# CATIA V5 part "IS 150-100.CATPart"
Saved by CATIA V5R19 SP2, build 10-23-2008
Part number: IS 150-100
Bounding box of the stored display mesh (mm): x -15.868 to 15.868, y -15.868 to 15.868, z 0 to 250
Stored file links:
  C:\Users\Bora\Desktop\3D Katı model\IS serisi\IS 150\IS 150-100.CATPart
  C:\Program Files\Dassault Systemes\B19\intel_a\reffiles\standard\MetricThickPitch.txt
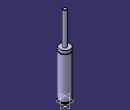
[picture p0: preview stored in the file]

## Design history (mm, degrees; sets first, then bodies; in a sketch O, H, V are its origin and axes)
Body1 (main body)
  Sketch1 on yz-plane, origin (0, 0, 0), H (0, 1, 0), V (0, 0, 1)
    point P3 (6, 249)
    point P5 (6, 249)
    point P7 (16, 138.5)
    point P8 (16, 136.5)
    point P12 (16, 136.5)
    point P13 (16, 138.5)
    line L1 (16, 0) -> (16, 4)
    line L2 (6, 249) -> (6, 148)
    arc A1 centre (5, 249) radius 1 from (6, 249) to (5, 250) ccw
    arc A2 centre (16, 137.5) radius 1 from (16, 138.5) to (16, 136.5) ccw
    line L3 (13.5, 7.5) -> (13.5, 4)
    line L4 (16, 7.5) -> (16, 136.5)
    line L5 (16, 138.5) -> (16, 148)
    line L6 (0, 0) -> (16, 0)
    line L7 (13.5, 4) -> (16, 4)
    line L8 (13.5, 7.5) -> (16, 7.5)
    line L9 (6, 148) -> (16, 148)
    line L10 (5, 250) -> (0, 250)
    point P15 (0, 250)
    horizontal: L6 H, L7 H, L8 H, L9 H
    tangency: L10 A1
    coincidence: P15 V, P3 P5, P7 P13, P8 P12
  Shaft1: profile Sketch1, axis Sketch1.V, angle 360
  Sketch2 on face of Shaft1 from Sketch1.L6, origin (0, 0, 0), H (1, 0, 0), V (0, -1, 0)
    point P1 (0, 0)
  Hole1: placed by Sketch2, at (0, 0, 0) direction (0, 0, 1), diameter 6.647, depth 7, threaded "M8", thread diameter 8, thread depth 7, pitch 1.25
